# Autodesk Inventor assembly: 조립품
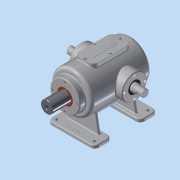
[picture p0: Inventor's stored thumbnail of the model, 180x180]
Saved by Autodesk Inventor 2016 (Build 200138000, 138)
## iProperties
Created: 2018-11
Part Number: 조립품
Material: 일반
Document SubType Name: Assembly
Designer: user
Author: user
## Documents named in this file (15)
- C:\Users\user\Desktop\381121V1005\조립품.iam
- C:\Users\user\Desktop\381121V1005\가변스프링.ipt
- C:\Users\user\Desktop\381121V1005\베어링 6205.ipt
- 베어링 6205.ipt
- C:\Users\user\Desktop\381121V1005\본체.ipt
- C:\Users\user\Desktop\381121V1005\볼트 M4x0.7.ipt
- C:\Users\user\Desktop\381121V1005\부시.ipt
- C:\Users\user\Desktop\381121V1005\상부커버.ipt
- C:\Users\user\Desktop\381121V1005\슬라이드 커버.ipt
- C:\Users\user\Desktop\381121V1005\슬라이드.ipt
- C:\Users\user\Desktop\381121V1005\오일실.ipt
- 오일실.ipt
- C:\Users\user\Desktop\381121V1005\육각머리볼트 M4.ipt
- C:\Users\user\Desktop\381121V1005\축 커버.ipt
- C:\Users\user\Desktop\381121V1005\편심축.ipt
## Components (13 placed, 2 different names)
1. 가변스프링:1
2. M4x0.7:3
3. M4x0.7:4
4. M4x0.7:5
5. M4x0.7:6
6. M4x0.7:1
7. M4x0.7:7
8. M4x0.7:8
9. M4x0.7:9
10. M4x0.7:2
11. M4x0.7:10
12. M4x0.7:11
13. M4x0.7:12
